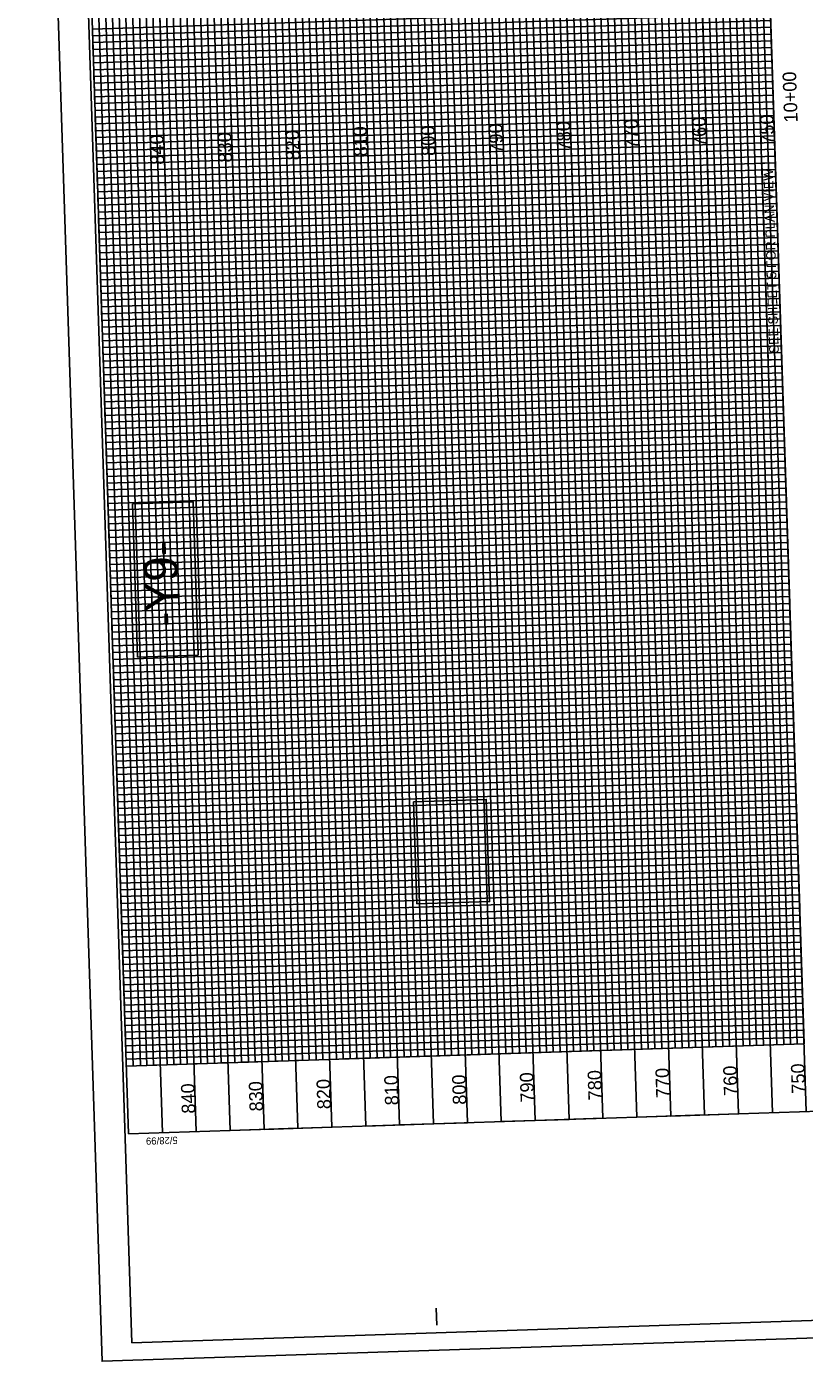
# Model space of a CAD drawing. Extents: x 1627314 to 1628469, y 762309 to 764253.
# Drawn here: x 1627314 to 1627888, y 762309 to 763293 of the extents above; entities that cross this region are included whole.
import ezdxf

# ---------------------------------------------------------------- set-up
doc = ezdxf.new("R2010")
doc.units = 0
for name, color, linetype in [('Exist Vertical Profile Horizontal Axis Label Major', 7, 'Continuous'), ('Exist Vertical Profile Vertical Axis Label', 7, 'Continuous'), ('Prop DSN Text', 7, 'Continuous'), ('Prop Grid Mask', 7, 'Continuous'), ('Sheet Data Field CELL', 7, 'Continuous'), ('Sheet DOT Grid CELL', 7, 'Continuous'), ('Sheet Layout Profile Border Port 1', 7, 'Continuous'), ('Sheet Plot Border Inside CELL', 7, 'Continuous'), ('Sheet Plot Border Outside CELL', 7, 'Continuous'), ('Sheet Profile CELL', 7, 'Continuous'), ('Sheet Profile Grid Major CELL', 7, 'Continuous'), ('Sheet Profile Grid Middle CELL', 7, 'Continuous'), ('Sheet Profile Grid Minor CELL', 7, 'Continuous')]:
    doc.layers.add(name, color=color, linetype=linetype)

msp = doc.modelspace()

# ---------------------------------------------------------------- linework, layer by layer
at = {"layer": 'Prop Grid Mask'}
for points in [[(1627366.44, 763176.67), (1627364.8, 763226.64), (1627864.53, 763242.99), (1627866.17, 763193.01)], [(1627856.17, 763192.69), (1627860.92, 763047.76), (1627870.91, 763048.09), (1627866.17, 763193.01)], [(1627440.71, 762829.99), (1627437.01, 762943.01), (1627392.29, 762941.55), (1627395.99, 762828.53)], [(1627601.89, 762646.53), (1627599.42, 762721.83), (1627653, 762723.58), (1627655.46, 762648.29)]]:
    msp.add_lwpolyline(points, close=True, dxfattribs=at)
at = {"layer": 'Sheet DOT Grid CELL'}
for p, q in [((1627590.15, 763984.41), (1627639.19, 762485.21)), ((1627640.12, 763986.05), (1627689.16, 762486.85)), ((1627690.1, 763987.68), (1627739.13, 762488.48)), ((1627740.07, 763989.32), (1627789.11, 762490.12)), ((1627790.04, 763990.95), (1627839.08, 762491.75)), ((1627396.8, 763777.93), (1627439.29, 762478.68)), ((1627446.77, 763779.57), (1627489.27, 762480.31)), ((1627496.74, 763781.25), (1627539.24, 762481.95)), ((1627546.72, 763782.83), (1627589.21, 762483.58)), ((1627862.9, 763292.96), (1627363.17, 763276.61)), ((1627864.53, 763242.99), (1627364.8, 763226.64)), ((1627866.17, 763193.01), (1627366.44, 763176.67)), ((1627867.8, 763143.04), (1627368.07, 763126.69)), ((1627869.44, 763093.07), (1627369.71, 763076.72)), ((1627871.07, 763043.09), (1627371.34, 763026.75)), ((1627872.71, 762993.12), (1627372.98, 762976.77)), ((1627874.34, 762943.15), (1627374.61, 762926.8)), ((1627875.98, 762893.17), (1627376.24, 762876.83)), ((1627877.61, 762843.2), (1627377.88, 762826.85)), ((1627879.25, 762793.23), (1627379.51, 762776.88)), ((1627880.88, 762743.25), (1627381.15, 762726.91)), ((1627882.52, 762693.28), (1627382.78, 762676.93)), ((1627884.15, 762643.31), (1627384.42, 762626.96)), ((1627885.78, 762593.33), (1627386.05, 762576.99)), ((1627887.42, 762543.36), (1627387.69, 762527.01))]:
    msp.add_line(p, q, dxfattribs=at)
at = {"layer": 'Sheet Layout Profile Border Port 1'}
msp.add_lwpolyline([(1627548.65, 762532.28), (1627887.42, 762543.36), (1627841.65, 763942.61), (1627566.8, 763933.62)], dxfattribs=at)
at = {"layer": 'Sheet Plot Border Inside CELL'}
msp.add_lwpolyline([(1628446.34, 762357.53), (1628391.86, 764023.14), (1627337.33, 763988.65), (1627391.81, 762323.04)], close=True, dxfattribs=at)
at = {"layer": 'Sheet Plot Border Outside CELL'}
msp.add_lwpolyline([(1628469.21, 762345.27), (1628413.63, 764044.37), (1627314.22, 764008.4), (1627369.79, 762309.31)], close=True, dxfattribs=at)
at = {"layer": 'Sheet Profile CELL'}
for p, q in [((1627889.05, 762493.39), (1627840.02, 763992.59)), ((1627616.56, 762335.89), (1627616.15, 762348.39))]:
    msp.add_line(p, q, dxfattribs=at)
msp.add_lwpolyline([(1627340.28, 763976.24), (1627389.32, 762477.04), (1628438.76, 762511.37), (1628389.72, 764010.57)], close=True, dxfattribs=at)
at = {"layer": 'Sheet Profile Grid Major CELL'}
for points in [[(1627546.71, 763782.88), (1627589.21, 762483.58), (1627639.19, 762485.21), (1627590.15, 763984.41)], [(1627640.12, 763986.05), (1627689.16, 762486.85), (1627739.13, 762488.48), (1627690.1, 763987.68)], [(1627740.07, 763989.32), (1627789.11, 762490.12), (1627789.11, 762490.12), (1627839.08, 762491.75), (1627790.04, 763990.95)], [(1627439.29, 762478.68), (1627396.79, 763777.98)], [(1627446.77, 763779.62), (1627489.27, 762480.31), (1627539.24, 762481.95), (1627496.74, 763781.25)], [(1627387.69, 762527.01), (1627887.42, 762543.36), (1627885.78, 762593.33), (1627386.05, 762576.99), (1627384.42, 762626.96), (1627884.15, 762643.31), (1627882.52, 762693.28), (1627382.78, 762676.93), (1627381.15, 762726.91), (1627880.88, 762743.25), (1627879.25, 762793.23), (1627379.51, 762776.88), (1627377.88, 762826.85), (1627877.61, 762843.2), (1627875.98, 762893.17), (1627376.24, 762876.83), (1627374.61, 762926.8), (1627874.34, 762943.15), (1627872.71, 762993.12), (1627372.98, 762976.77), (1627371.34, 763026.75), (1627871.07, 763043.09), (1627869.44, 763093.07), (1627369.71, 763076.72), (1627368.07, 763126.69), (1627867.8, 763143.04), (1627866.17, 763193.01), (1627366.44, 763176.67), (1627364.8, 763226.64), (1627864.53, 763242.99), (1627862.9, 763292.96), (1627363.17, 763276.61), (1627361.53, 763326.59)]]:
    msp.add_lwpolyline(points, dxfattribs=at)
at = {"layer": 'Sheet Profile Grid Middle CELL'}
msp.add_line((1627414.31, 762477.86), (1627371.81, 763777.11), dxfattribs=at)
for points in [[(1627815.03, 763991.77), (1627864.07, 762492.57)], [(1627615.14, 763985.23), (1627664.17, 762486.03), (1627714.15, 762487.67), (1627665.11, 763986.86)], [(1627715.08, 763988.5), (1627764.12, 762489.3), (1627814.09, 762490.94), (1627765.06, 763990.13)], [(1627521.73, 763782.02), (1627564.23, 762482.76), (1627614.2, 762484.4), (1627570.88, 763808.69)], [(1627421.78, 763778.8), (1627464.28, 762479.49), (1627514.25, 762481.13), (1627471.75, 763780.43)], [(1627386.87, 762552), (1627886.6, 762568.35), (1627884.97, 762618.32), (1627385.23, 762601.97), (1627383.6, 762651.95), (1627883.33, 762668.29), (1627881.7, 762718.27), (1627381.97, 762701.92), (1627380.33, 762751.89), (1627880.06, 762768.24), (1627878.43, 762818.21), (1627378.7, 762801.87), (1627377.06, 762851.84), (1627876.79, 762868.19), (1627875.16, 762918.16), (1627375.43, 762901.81), (1627373.79, 762951.79), (1627873.53, 762968.13), (1627871.89, 763018.11), (1627372.16, 763001.76), (1627370.52, 763051.73), (1627870.26, 763068.08), (1627868.62, 763118.05), (1627868.62, 763118.05), (1627368.89, 763101.71), (1627367.25, 763151.68), (1627866.99, 763168.03), (1627865.35, 763218), (1627365.62, 763201.65), (1627363.98, 763251.63), (1627863.72, 763267.97), (1627862.08, 763317.95)]]:
    msp.add_lwpolyline(points, dxfattribs=at)
at = {"layer": 'Sheet Profile Grid Minor CELL'}
for p, q in [((1627867.43, 762542.71), (1627821.66, 763941.96)), ((1627826.66, 763942.12), (1627872.43, 762542.87)), ((1627877.42, 762543.03), (1627831.66, 763942.29)), ((1627576.79, 763933.95), (1627622.56, 762534.7)), ((1627627.56, 762534.86), (1627581.79, 763934.11)), ((1627586.79, 763934.28), (1627632.56, 762535.02)), ((1627642.55, 762535.35), (1627596.78, 763934.6)), ((1627601.78, 763934.77), (1627647.55, 762535.51)), ((1627652.55, 762535.68), (1627606.78, 763934.93)), ((1627611.77, 763935.09), (1627657.54, 762535.84)), ((1627667.54, 762536.17), (1627621.77, 763935.42)), ((1627626.77, 763935.58), (1627672.53, 762536.33)), ((1627677.53, 762536.5), (1627631.76, 763935.75)), ((1627636.76, 763935.91), (1627682.53, 762536.66)), ((1627692.52, 762536.99), (1627646.75, 763936.24)), ((1627651.75, 763936.4), (1627697.52, 762537.15)), ((1627702.52, 762537.31), (1627656.75, 763936.56)), ((1627661.75, 763936.73), (1627707.52, 762537.48)), ((1627717.51, 762537.8), (1627671.74, 763937.05)), ((1627676.74, 763937.22), (1627722.51, 762537.97)), ((1627727.51, 762538.13), (1627681.74, 763937.38)), ((1627686.73, 763937.55), (1627732.5, 762538.29)), ((1627742.5, 762538.62), (1627696.73, 763937.87)), ((1627701.73, 763938.04), (1627747.49, 762538.78)), ((1627752.49, 762538.95), (1627706.72, 763938.2)), ((1627711.72, 763938.36), (1627757.49, 762539.11)), ((1627767.48, 762539.44), (1627721.71, 763938.69)), ((1627726.71, 763938.85), (1627772.48, 762539.6)), ((1627731.71, 763939.02), (1627777.48, 762539.76)), ((1627736.71, 763939.18), (1627782.48, 762539.93)), ((1627792.47, 762540.25), (1627746.7, 763939.51)), ((1627751.7, 763939.67), (1627797.47, 762540.42)), ((1627802.47, 762540.58), (1627756.7, 763939.83)), ((1627761.69, 763940), (1627807.46, 762540.75)), ((1627817.46, 762541.07), (1627771.69, 763940.32)), ((1627776.69, 763940.49), (1627822.45, 762541.24)), ((1627827.45, 762541.4), (1627781.68, 763940.65)), ((1627786.68, 763940.81), (1627832.45, 762541.56)), ((1627842.44, 762541.89), (1627796.67, 763941.14)), ((1627801.67, 763941.3), (1627847.44, 762542.05)), ((1627852.44, 762542.22), (1627806.67, 763941.47)), ((1627811.67, 763941.63), (1627857.44, 762542.38)), ((1627392.68, 762527.18), (1627351.82, 763776.51)), ((1627356.82, 763776.67), (1627398.03, 762527.35)), ((1627402.68, 762527.5), (1627361.81, 763776.84)), ((1627481.75, 763780.71), (1627522.61, 762531.43)), ((1627486.75, 763780.92), (1627527.61, 762531.59)), ((1627491.74, 763781.09), (1627532.61, 762531.75)), ((1627542.6, 762532.08), (1627501.74, 763781.41)), ((1627506.74, 763781.58), (1627547.6, 762532.25)), ((1627552.6, 762532.41), (1627511.73, 763781.69)), ((1627531.72, 763782.34), (1627572.59, 762533.06)), ((1627577.59, 762533.23), (1627536.72, 763782.51)), ((1627556.71, 763783.16), (1627597.57, 762533.88)), ((1627602.57, 762534.04), (1627561.71, 763783.33)), ((1627397.68, 762527.34), (1627397.68, 762527.34))]:
    msp.add_line(p, q, dxfattribs=at)
for points in [[(1627836.65, 763942.45), (1627882.42, 762543.2)], [(1627566.71, 763783.49), (1627607.57, 762534.21), (1627617.56, 762534.53), (1627571.79, 763933.79)], [(1627366.81, 763777), (1627407.68, 762527.67), (1627417.67, 762528), (1627376.81, 763777.33)], [(1627381.8, 763777.44), (1627422.67, 762528.16), (1627427.67, 762528.32), (1627386.8, 763777.65)], [(1627391.8, 763777.82), (1627432.66, 762528.49), (1627442.66, 762528.81), (1627401.79, 763778.14)], [(1627406.79, 763778.31), (1627447.65, 762528.98), (1627452.65, 762529.14), (1627411.79, 763778.47)], [(1627416.78, 763778.63), (1627457.65, 762529.3), (1627467.64, 762529.63), (1627426.78, 763778.96)], [(1627431.78, 763779.13), (1627472.64, 762529.79), (1627477.64, 762529.96), (1627436.77, 763779.29)], [(1627441.77, 763779.45), (1627482.64, 762530.12), (1627492.63, 762530.45), (1627451.77, 763779.78)], [(1627456.86, 763779.95), (1627497.72, 762530.71), (1627502.62, 762530.87), (1627461.76, 763780.11)], [(1627466.76, 763780.27), (1627507.62, 762530.94), (1627517.62, 762531.26), (1627476.75, 763780.6)], [(1627516.73, 763781.85), (1627557.6, 762532.57), (1627567.59, 762532.9), (1627526.73, 763782.18)], [(1627541.72, 763782.67), (1627582.58, 762533.39), (1627592.58, 762533.72), (1627551.71, 763783)], [(1627862.57, 763302.95), (1627362.84, 763286.61), (1627362.68, 763291.61), (1627862.41, 763307.95)], [(1627370.36, 763056.73), (1627870.09, 763073.08), (1627869.93, 763078.07), (1627370.2, 763061.73), (1627370.03, 763066.73), (1627869.77, 763083.07), (1627869.6, 763088.07), (1627369.87, 763071.72), (1627369.54, 763081.72), (1627869.28, 763098.06), (1627869.11, 763103.06), (1627369.38, 763086.72), (1627369.22, 763091.71), (1627868.95, 763108.06), (1627868.78, 763113.06), (1627369.05, 763096.71), (1627368.73, 763106.7), (1627868.46, 763123.05), (1627868.29, 763128.05), (1627368.56, 763111.7), (1627368.4, 763116.7), (1627868.13, 763133.05), (1627867.97, 763138.04), (1627368.23, 763121.7), (1627367.91, 763131.69), (1627867.64, 763148.04), (1627867.48, 763153.03), (1627367.74, 763136.69), (1627367.58, 763141.69), (1627867.31, 763158.03), (1627867.15, 763163.03), (1627367.42, 763146.68), (1627367.09, 763156.68), (1627866.82, 763173.02), (1627866.66, 763178.02), (1627366.93, 763161.68), (1627366.76, 763166.67), (1627866.5, 763183.02), (1627866.33, 763188.02), (1627366.6, 763171.67), (1627366.27, 763181.66), (1627866.01, 763198.01), (1627866.01, 763198.01), (1627865.84, 763203.01), (1627366.11, 763186.66), (1627365.95, 763191.66), (1627865.68, 763208.01), (1627865.52, 763213), (1627365.78, 763196.66), (1627365.46, 763206.65), (1627865.19, 763223), (1627865.03, 763227.99), (1627365.29, 763211.65), (1627365.13, 763216.65), (1627864.86, 763232.99), (1627864.7, 763237.99), (1627364.97, 763221.64), (1627364.64, 763231.64), (1627864.37, 763247.98), (1627864.21, 763252.98), (1627364.48, 763236.63), (1627364.31, 763241.63), (1627864.04, 763257.98), (1627863.88, 763262.98), (1627364.15, 763246.63), (1627363.82, 763256.62), (1627863.55, 763272.97), (1627863.39, 763277.97), (1627363.66, 763261.62), (1627363.49, 763266.62), (1627863.23, 763282.97), (1627863.06, 763287.96), (1627363.33, 763271.62), (1627363, 763281.61), (1627862.74, 763297.96)], [(1627880.39, 762758.25), (1627880.23, 762763.24), (1627380.49, 762746.9), (1627380.17, 762756.89), (1627879.9, 762773.24), (1627879.74, 762778.24), (1627380, 762761.89), (1627379.84, 762766.89), (1627879.57, 762783.23), (1627879.41, 762788.23), (1627379.68, 762771.88), (1627379.35, 762781.88), (1627879.08, 762798.22), (1627878.92, 762803.22), (1627379.19, 762786.88), (1627379.02, 762791.87), (1627878.76, 762808.22), (1627878.59, 762813.22), (1627378.86, 762796.87), (1627378.53, 762806.86), (1627878.27, 762823.21), (1627878.1, 762828.21), (1627378.37, 762811.86), (1627378.21, 762816.86), (1627877.94, 762833.21), (1627877.78, 762838.2), (1627378.04, 762821.86), (1627377.72, 762831.85), (1627877.45, 762848.2), (1627877.28, 762853.19), (1627377.55, 762836.85), (1627377.39, 762841.85), (1627877.12, 762858.19), (1627876.96, 762863.19), (1627377.23, 762846.84), (1627376.9, 762856.84), (1627876.63, 762873.18), (1627876.47, 762878.18), (1627376.73, 762861.84), (1627376.57, 762866.83), (1627876.3, 762883.18), (1627876.14, 762888.18), (1627376.41, 762871.83), (1627376.08, 762881.82), (1627875.81, 762898.17), (1627875.65, 762903.17), (1627375.92, 762886.82), (1627375.75, 762891.82), (1627875.49, 762908.17), (1627875.32, 762913.16), (1627375.59, 762896.82), (1627375.26, 762906.81), (1627875, 762923.16), (1627874.83, 762928.15), (1627375.1, 762911.81), (1627374.94, 762916.81), (1627874.67, 762933.15), (1627874.51, 762938.15), (1627374.77, 762921.8), (1627374.45, 762931.8), (1627874.18, 762948.14), (1627874.02, 762953.14), (1627374.28, 762936.8), (1627374.12, 762941.79), (1627873.85, 762958.14), (1627873.69, 762963.14), (1627373.96, 762946.79), (1627373.63, 762956.78), (1627873.36, 762973.13), (1627873.2, 762978.13), (1627373.47, 762961.78), (1627373.3, 762966.78), (1627873.03, 762983.13), (1627872.87, 762988.12), (1627373.14, 762971.78), (1627372.81, 762981.77), (1627872.54, 762998.12), (1627872.38, 763003.11), (1627372.65, 762986.77), (1627372.48, 762991.77), (1627872.22, 763008.11), (1627872.05, 763013.11), (1627372.32, 762996.76), (1627371.99, 763006.76), (1627871.73, 763023.1), (1627871.56, 763028.1), (1627371.83, 763011.76), (1627371.67, 763016.75), (1627871.4, 763033.1), (1627871.24, 763038.1), (1627371.5, 763021.75), (1627371.18, 763031.74), (1627870.91, 763048.09), (1627870.75, 763053.09), (1627371.01, 763036.74), (1627370.85, 763041.74), (1627870.58, 763058.09), (1627870.42, 763063.08), (1627370.69, 763046.74), (1627370.36, 763056.73)], [(1627387.52, 762532.01), (1627887.26, 762548.36), (1627887.09, 762553.36), (1627387.36, 762537.01), (1627387.2, 762542.01), (1627886.93, 762558.35), (1627886.77, 762563.35), (1627387.03, 762547), (1627386.71, 762557), (1627886.44, 762573.34), (1627886.28, 762578.34), (1627386.54, 762562), (1627386.38, 762566.99), (1627886.11, 762583.34), (1627885.95, 762588.34), (1627885.62, 762598.33), (1627885.46, 762603.33), (1627385.73, 762586.98), (1627385.56, 762591.98), (1627885.29, 762608.33), (1627885.13, 762613.32), (1627385.4, 762596.98), (1627385.07, 762606.97), (1627884.8, 762623.32), (1627884.64, 762628.32), (1627384.91, 762611.97), (1627384.74, 762616.97), (1627884.48, 762633.31), (1627884.31, 762638.31), (1627384.58, 762621.96), (1627384.25, 762631.96), (1627883.99, 762648.3), (1627883.82, 762653.3), (1627384.09, 762636.96), (1627383.93, 762641.95), (1627883.66, 762658.3), (1627883.5, 762663.3), (1627383.76, 762646.95), (1627383.44, 762656.95), (1627883.17, 762673.29), (1627883.01, 762678.29), (1627383.27, 762661.94), (1627383.11, 762666.94), (1627882.84, 762683.29), (1627882.68, 762688.28), (1627382.95, 762671.94), (1627382.62, 762681.93), (1627882.35, 762698.28), (1627882.19, 762703.28), (1627382.46, 762686.93), (1627382.29, 762691.93), (1627882.03, 762708.27), (1627881.86, 762713.27), (1627382.13, 762696.92), (1627381.8, 762706.92), (1627881.53, 762723.26), (1627881.37, 762728.26), (1627381.64, 762711.92), (1627381.48, 762716.91), (1627881.21, 762733.26), (1627881.04, 762738.26), (1627381.31, 762721.91), (1627380.98, 762731.9), (1627880.72, 762748.25), (1627880.55, 762753.25), (1627380.82, 762736.9), (1627380.66, 762741.9), (1627880.39, 762758.25)], [(1627885.95, 762588.34), (1627386.22, 762571.99), (1627385.89, 762581.99), (1627885.62, 762598.33)]]:
    msp.add_lwpolyline(points, dxfattribs=at)

# ---------------------------------------------------------------- texts
at = {"layer": 'Exist Vertical Profile Horizontal Axis Label Major'}
msp.add_text('10+00', height=10, rotation=91.87347, dxfattribs=at).set_placement((1627882.7, 763222.88))
at = {"layer": 'Exist Vertical Profile Vertical Axis Label'}
for s, p in [('770', (1627765.53, 763203.16)), ('760', (1627815.51, 763204.8)), ('750', (1627865.48, 763206.43)), ('830', (1627465.69, 763193.35)), ('820', (1627515.67, 763194.99)), ('810', (1627565.6, 763197.82)), ('800', (1627615.61, 763198.26)), ('790', (1627665.59, 763199.89)), ('780', (1627715.56, 763201.53)), ('840', (1627415.72, 763191.72)), ('770', (1627788.42, 762503.53)), ('760', (1627838.39, 762505.17)), ('750', (1627888.37, 762506.8)), ('830', (1627488.58, 762493.73)), ('820', (1627538.55, 762495.36)), ('810', (1627588.49, 762498.19)), ('800', (1627638.5, 762498.63)), ('790', (1627688.47, 762500.27)), ('780', (1627738.45, 762501.9)), ('840', (1627438.61, 762492.09))]:
    msp.add_text(s, height=10, rotation=91.87347, dxfattribs=at).set_placement(p)
at = {"layer": 'Prop DSN Text'}
msp.add_text('SEE SHEET 5 FOR PLAN VIEW', height=7, rotation=91.87347, dxfattribs=at).set_placement((1627868.81, 763052.61))
at = {"layer": 'Sheet Data Field CELL'}
msp.add_text('-Y9-', height=25, rotation=91.87347, dxfattribs=at).set_placement((1627426.96, 762851.27))
at = {"layer": 'Sheet Profile CELL'}
msp.add_text('5/28/99', height=5.25, rotation=181.87347, dxfattribs=at).set_placement((1627425.5, 762474.99))

doc.saveas('drawing.dxf')
